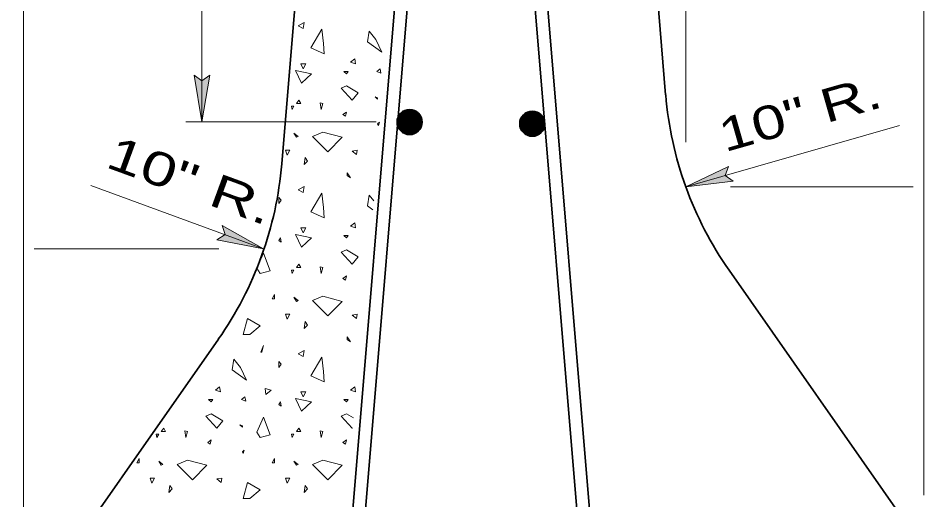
# Model space of a CAD drawing. Extents: x -9.07 to -2.08, y 8.04 to 17.77.
# Drawn here: x -6.82 to -5.197, y 14.699 to 15.562 of the extents above; entities that cross this region are included whole.
import ezdxf
from ezdxf.enums import TextEntityAlignment as Align

# ---------------------------------------------------------------- set-up
doc = ezdxf.new("R2010")
doc.units = 0
doc.header["$LTSCALE"] = 0.024
for name, color, linetype, lineweight in [('1', 7, 'Continuous', 35), ('10', 7, 'Continuous', 13), ('12', 7, 'Continuous', 53), ('6', 7, 'Continuous', 13)]:
    doc.layers.add(name, color=color, linetype=linetype, lineweight=lineweight)

msp = doc.modelspace()

# ---------------------------------------------------------------- hatches: boundary and pattern name
at = {"layer": '10'}
for points in [[(-6.491, 15.376), (-6.477, 15.46), (-6.491, 15.4495), (-6.505, 15.46)], [(-5.624, 15.26), (-5.53933, 15.26967), (-5.55333, 15.28017), (-5.54717, 15.2965)], [(-6.3805, 15.14883), (-6.4545, 15.19083), (-6.4495, 15.17417), (-6.46417, 15.16467)]]:
    msp.add_hatch(color=256, dxfattribs=at).paths.add_polyline_path(points)

# ---------------------------------------------------------------- linework, layer by layer
at = {"layer": '1'}
for p, q in [((-5.754, 16.55317), (-5.66, 15.4245)), ((-6.284, 13.922), (-6.107, 16.04583)), ((-6.26133, 13.922), (-6.08433, 16.04483)), ((-5.93267, 16.04483), (-5.75567, 13.922)), ((-5.91, 16.04583), (-5.73283, 13.922)), ((-5.54633, 15.11033), (-5.19733, 14.6115))]:
    msp.add_line(p, q, dxfattribs=at)
for points in [[(-6.348, 15.30083), (-6.25383, 16.42933), (-6.25383, 16.55317)], [(-7.227, 13.773), (-7.227, 14.29567), (-6.81067, 14.29567), (-6.81067, 14.48783), (-6.4615, 14.98667)]]:
    msp.add_lwpolyline(points, dxfattribs=at)
for centre, radius in [((-6.11876, 15.37584), 0.02253), ((-6.11896, 15.37603), 0.02103), ((-6.12098, 15.37603), 0.01823), ((-6.11871, 15.3755), 0.02028), ((-6.11811, 15.37454), 0.01988), ((-6.11821, 15.37525), 0.0185), ((-6.12023, 15.37692), 0.01508), ((-6.11772, 15.37515), 0.01751), ((-6.11757, 15.37465), 0.0166), ((-6.12059, 15.37515), 0.01309), ((-6.11733, 15.3744), 0.01584), ((-6.11757, 15.37401), 0.0151), ((-6.11718, 15.37401), 0.01471), ((-6.11747, 15.37426), 0.01421), ((-6.11683, 15.37391), 0.01358), ((-6.11669, 15.37415), 0.01272), ((-6.11658, 15.3743), 0.01184), ((-6.11658, 15.37454), 0.01085), ((-5.89905, 15.37284), 0.02253), ((-5.89924, 15.37303), 0.02103), ((-5.90126, 15.37303), 0.01823), ((-5.89899, 15.3725), 0.02028), ((-5.89839, 15.37154), 0.01988), ((-5.8985, 15.37225), 0.0185), ((-5.90052, 15.37392), 0.01508), ((-5.898, 15.37215), 0.01751), ((-5.89786, 15.37165), 0.0166), ((-5.89761, 15.3714), 0.01584), ((-5.89786, 15.37101), 0.0151), ((-5.89747, 15.37101), 0.01471), ((-5.89775, 15.37126), 0.01421), ((-6.12172, 15.3744), 0.01045), ((-6.11998, 15.3749), 0.00844), ((-6.11644, 15.37426), 0.01021), ((-6.11644, 15.37415), 0.00921), ((-6.11605, 15.37337), 0.00882), ((-6.11584, 15.37327), 0.00805), ((-6.11584, 15.37348), 0.00706), ((-6.11555, 15.37366), 0.00681), ((-6.11555, 15.37302), 0.00627), ((-6.11531, 15.37352), 0.00602), ((-6.1152, 15.37337), 0.00515), ((-6.11555, 15.37376), 0.0043), ((-6.11506, 15.37323), 0.00382), ((-6.11492, 15.37327), 0.00316), ((-6.11467, 15.37313), 0.00241), ((-6.11467, 15.37337), 0.00213), ((-6.11392, 15.37327), 0.00267), ((-6.1147, 15.37337), 0.00139), ((-6.11495, 15.37337), 0.000653), ((-6.11442, 15.37337), 0.000415), ((-5.90087, 15.37215), 0.01309), ((-5.90201, 15.3714), 0.01045), ((-5.89711, 15.37091), 0.01358), ((-5.89697, 15.37115), 0.01272), ((-5.89687, 15.3713), 0.01184), ((-5.90027, 15.3719), 0.00844), ((-5.89687, 15.37154), 0.01085), ((-5.89673, 15.37126), 0.01021), ((-5.89673, 15.37115), 0.00921), ((-5.89634, 15.37037), 0.00882), ((-5.89612, 15.37027), 0.00805), ((-5.89612, 15.37048), 0.00706), ((-5.89584, 15.37066), 0.00681), ((-5.89584, 15.37002), 0.00627), ((-5.89559, 15.37052), 0.00602), ((-5.89548, 15.37037), 0.00515), ((-5.89584, 15.37076), 0.0043), ((-5.89534, 15.37023), 0.00382), ((-5.8952, 15.37027), 0.00316), ((-5.89495, 15.37013), 0.00241), ((-5.89495, 15.37037), 0.00213), ((-5.89421, 15.37027), 0.00267), ((-5.89499, 15.37037), 0.00139), ((-5.89524, 15.37037), 0.000653), ((-5.89471, 15.37037), 0.000415)]:
    msp.add_circle(centre, radius, dxfattribs=at)
for centre, start, end in [((-5.02168, 15.4777), 184.76364, 214.99201), ((-6.98624, 15.35395), 325.00798, 355.23636)]:
    msp.add_arc(centre, 0.6405, start, end, dxfattribs=at)
at = {"layer": '10'}
for p, q in [((-6.81067, 17.69383), (-6.81067, 14.55983)), ((-5.19733, 14.70767), (-5.19733, 16.59683)), ((-6.491, 16.14433), (-6.491, 15.376)), ((-5.624, 15.34), (-5.624, 15.8185)), ((-6.505, 15.46), (-6.491, 15.376)), ((-6.505, 15.46), (-6.491, 15.4495)), ((-6.477, 15.46), (-6.491, 15.376)), ((-6.477, 15.46), (-6.491, 15.4495)), ((-6.17883, 15.376), (-6.51983, 15.376)), ((-5.624, 15.26), (-5.241, 15.36983)), ((-5.54717, 15.2965), (-5.624, 15.26)), ((-5.54717, 15.2965), (-5.55333, 15.28017)), ((-5.53933, 15.26967), (-5.55333, 15.28017)), ((-6.3805, 15.14883), (-6.69017, 15.26233)), ((-5.53933, 15.26967), (-5.624, 15.26)), ((-5.2165, 15.26), (-5.544, 15.26)), ((-6.4545, 15.19083), (-6.3805, 15.14883)), ((-6.4545, 15.19083), (-6.4495, 15.17417)), ((-6.46417, 15.16467), (-6.4495, 15.17417)), ((-6.46417, 15.16467), (-6.3805, 15.14883)), ((-6.7915, 15.14883), (-6.4605, 15.14883))]:
    msp.add_line(p, q, dxfattribs=at)
for points in [[(-6.491, 15.376), (-6.477, 15.46), (-6.491, 15.4495), (-6.505, 15.46)], [(-5.624, 15.26), (-5.53933, 15.26967), (-5.55333, 15.28017), (-5.54717, 15.2965)], [(-6.3805, 15.14883), (-6.4545, 15.19083), (-6.4495, 15.17417), (-6.46417, 15.16467)]]:
    msp.add_lwpolyline(points, close=True, dxfattribs=at)
at = {"layer": '6'}
for points in [[(-6.3185, 15.54833), (-6.3095, 15.54367), (-6.308, 15.5545)], [(-6.27317, 15.51633), (-6.27167, 15.49833), (-6.29583, 15.50883), (-6.276, 15.54233)], [(-6.19133, 15.539), (-6.19433, 15.5195), (-6.16867, 15.50117), (-6.17917, 15.52383)], [(-6.217, 15.48933), (-6.2245, 15.48317), (-6.2155, 15.48)], [(-6.32317, 15.468), (-6.31233, 15.44533), (-6.29433, 15.462)], [(-6.31383, 15.48), (-6.3095, 15.471), (-6.30483, 15.48)], [(-6.23667, 15.46667), (-6.232, 15.462), (-6.22917, 15.46667)], [(-6.17767, 15.46667), (-6.17017, 15.46333), (-6.1715, 15.471)], [(-6.2415, 15.43633), (-6.22167, 15.41517), (-6.21083, 15.4285), (-6.232, 15.44067)], [(-6.17633, 15.4195), (-6.1805, 15.42083), (-6.17633, 15.41667)], [(-6.33067, 15.40433), (-6.32933, 15.39817), (-6.326, 15.40433)], [(-6.317, 15.41517), (-6.31383, 15.409), (-6.32133, 15.409)], [(-6.27917, 15.4105), (-6.2775, 15.39817), (-6.2745, 15.409)], [(-6.23817, 15.38917), (-6.23383, 15.38633), (-6.232, 15.39383)], [(-6.173, 15.3755), (-6.17633, 15.37267), (-6.1745, 15.3695)], [(-6.32133, 15.3485), (-6.3185, 15.35), (-6.326, 15.35617)], [(-6.2745, 15.3575), (-6.23967, 15.3485), (-6.2655, 15.32267), (-6.29283, 15.35)], [(-6.34117, 15.3255), (-6.33833, 15.3165), (-6.33367, 15.3255)], [(-6.22167, 15.324), (-6.214, 15.318), (-6.21267, 15.3255)], [(-6.30617, 15.31217), (-6.308, 15.3), (-6.30183, 15.306)], [(-6.23067, 15.28483), (-6.23067, 15.28017), (-6.2245, 15.27583)], [(-6.3185, 15.2545), (-6.3095, 15.24983), (-6.308, 15.26067)], [(-6.35333, 15.24083), (-6.35333, 15.23), (-6.34867, 15.23617)], [(-6.27317, 15.2225), (-6.27167, 15.2045), (-6.29583, 15.215), (-6.276, 15.2485)], [(-6.217, 15.1955), (-6.2245, 15.18933), (-6.2155, 15.18617)], [(-6.32317, 15.17433), (-6.31233, 15.15167), (-6.29433, 15.16817)], [(-6.31383, 15.18617), (-6.3095, 15.17717), (-6.30483, 15.18617)], [(-6.35333, 15.1635), (-6.34867, 15.16067), (-6.35017, 15.16817)], [(-6.23667, 15.17283), (-6.232, 15.16817), (-6.22917, 15.17283)], [(-6.2415, 15.14267), (-6.22167, 15.12133), (-6.21083, 15.13467), (-6.232, 15.14683)], [(-6.3865, 15.1045), (-6.3685, 15.10917), (-6.38083, 15.14083), (-6.39267, 15.11383)], [(-6.33067, 15.1105), (-6.32933, 15.1045), (-6.326, 15.1105)], [(-6.317, 15.12133), (-6.31383, 15.11517), (-6.32133, 15.11517)], [(-6.27917, 15.11667), (-6.2775, 15.1045), (-6.2745, 15.11517)], [(-6.23817, 15.0955), (-6.23383, 15.0925), (-6.232, 15.10017)], [(-6.361, 15.06667), (-6.36533, 15.059), (-6.361, 15.059)], [(-6.32133, 15.05467), (-6.3185, 15.05617), (-6.326, 15.06233)], [(-6.2745, 15.06367), (-6.23967, 15.05467), (-6.2655, 15.02883), (-6.29283, 15.05617)], [(-6.34117, 15.03167), (-6.33833, 15.02267), (-6.33367, 15.03167)], [(-6.22167, 15.03017), (-6.214, 15.02417), (-6.21267, 15.03167)], [(-6.40483, 14.99533), (-6.3865, 15.01083), (-6.40917, 15.02417), (-6.41683, 14.99533)], [(-6.30617, 15.01833), (-6.308, 15.00617), (-6.30183, 15.01217)], [(-6.23067, 14.991), (-6.23067, 14.98633), (-6.2245, 14.982)], [(-6.38517, 14.96367), (-6.38367, 14.96367), (-6.38083, 14.97583)], [(-6.3185, 14.96083), (-6.3095, 14.956), (-6.308, 14.96683)], [(-6.43367, 14.95133), (-6.4365, 14.932), (-6.411, 14.91367), (-6.4215, 14.93633)], [(-6.27317, 14.92867), (-6.27167, 14.91067), (-6.29583, 14.92117), (-6.276, 14.95467)], [(-6.35333, 14.947), (-6.35333, 14.93633), (-6.34867, 14.94233)], [(-6.45933, 14.90167), (-6.46683, 14.89567), (-6.45783, 14.89233)], [(-6.3775, 14.8985), (-6.37617, 14.888), (-6.367, 14.89567)], [(-6.217, 14.90167), (-6.2245, 14.89567), (-6.2155, 14.89233)], [(-6.42, 14.879), (-6.4125, 14.87583), (-6.41383, 14.88333)], [(-6.31383, 14.89233), (-6.3095, 14.88333), (-6.30483, 14.89233)], [(-6.479, 14.879), (-6.47433, 14.87433), (-6.4715, 14.879)], [(-6.35333, 14.86967), (-6.34867, 14.86683), (-6.35017, 14.87433)], [(-6.32317, 14.8805), (-6.31233, 14.85783), (-6.29433, 14.87433)], [(-6.23667, 14.879), (-6.232, 14.87433), (-6.22917, 14.879)], [(-6.48367, 14.84883), (-6.464, 14.8275), (-6.45317, 14.84083), (-6.47433, 14.85317)], [(-6.3865, 14.81067), (-6.3685, 14.81533), (-6.38083, 14.847), (-6.39267, 14.82)], [(-6.55933, 14.8275), (-6.55617, 14.82133), (-6.56367, 14.82133)], [(-6.5215, 14.82283), (-6.51967, 14.81067), (-6.51683, 14.82133)], [(-6.4185, 14.83183), (-6.42283, 14.83333), (-6.4185, 14.829)], [(-6.317, 14.8275), (-6.31383, 14.82133), (-6.32133, 14.82133)], [(-6.27917, 14.82283), (-6.2775, 14.81067), (-6.2745, 14.82133)], [(-6.573, 14.81667), (-6.57167, 14.81067), (-6.56833, 14.81667)], [(-6.4805, 14.80167), (-6.47617, 14.79867), (-6.47433, 14.80633)], [(-6.33067, 14.81667), (-6.32933, 14.81067), (-6.326, 14.81667)], [(-6.23817, 14.80167), (-6.23383, 14.79867), (-6.232, 14.80633)], [(-6.41533, 14.788), (-6.4185, 14.785), (-6.41683, 14.78183)], [(-6.60333, 14.77283), (-6.60767, 14.76517), (-6.60333, 14.76517)], [(-6.51683, 14.77), (-6.482, 14.761), (-6.50783, 14.735), (-6.53517, 14.76233)], [(-6.361, 14.77283), (-6.36533, 14.76517), (-6.361, 14.76517)], [(-6.2745, 14.77), (-6.23967, 14.761), (-6.2655, 14.735), (-6.29283, 14.76233)], [(-6.56367, 14.761), (-6.56083, 14.76233), (-6.56833, 14.7685)], [(-6.32133, 14.761), (-6.3185, 14.76233), (-6.326, 14.7685)], [(-6.5835, 14.73783), (-6.58067, 14.72883), (-6.57583, 14.73783)], [(-6.464, 14.7365), (-6.45633, 14.73033), (-6.455, 14.73783)], [(-6.34117, 14.73783), (-6.33833, 14.72883), (-6.33367, 14.73783)], [(-6.5485, 14.7245), (-6.55033, 14.71233), (-6.54417, 14.7185)], [(-6.40483, 14.7015), (-6.3865, 14.717), (-6.40917, 14.73033), (-6.41683, 14.7015)], [(-6.30617, 14.7245), (-6.308, 14.71233), (-6.30183, 14.7185)]]:
    msp.add_lwpolyline(points, close=True, dxfattribs=at)
for points in [[(-6.183, 15.23483), (-6.19133, 15.24517), (-6.19433, 15.22583), (-6.1845, 15.21883)], [(-6.2195, 14.84583), (-6.232, 14.85317), (-6.2415, 14.84883), (-6.22167, 14.8275), (-6.22117, 14.82817)]]:
    msp.add_lwpolyline(points, dxfattribs=at)

# ---------------------------------------------------------------- texts
at = {"layer": '12'}
for rotation, width, p in [(16.005, 1.35, (-5.41127, 15.36251)), (339.866, 1.4, (-6.5212, 15.24295))]:
    msp.add_text('10" R.', height=0.06001, rotation=rotation, dxfattribs=dict(at, width=width)).set_placement(p, align=Align.CENTER)

doc.saveas('drawing.dxf')
